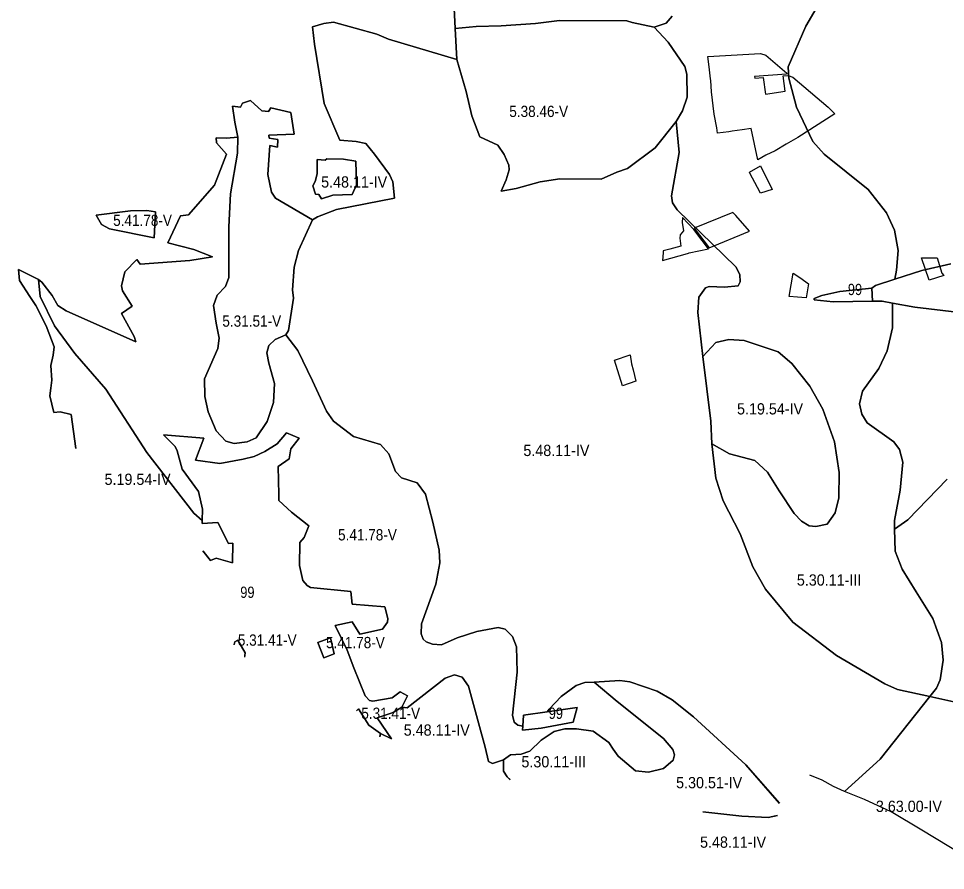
# Model space of a CAD drawing. Extents: x -589769 to -586623, y -1119592 to -1116833.
# Drawn here: x -589769 to -588124, y -1119592 to -1118080 of the extents above; entities that cross this region are included whole.
import ezdxf

# ---------------------------------------------------------------- set-up
doc = ezdxf.new("R2010")
doc.units = 0
doc.header["$LTSCALE"] = 8
doc.layers.add('40', color=7, linetype='Continuous', lineweight=25)
doc.layers.add('8', color=7, linetype='Continuous', lineweight=25)
doc.layers.add('41', color=7, linetype='Continuous')

msp = doc.modelspace()

# ---------------------------------------------------------------- linework, layer by layer
at = {"layer": '40'}
for points in [[(-588114.5, -1118516), (-588165.5, -1118527.5), (-588213.5, -1118543), (-588210.5, -1118527), (-588208, -1118492), (-588214.5, -1118456), (-588228.5, -1118425.5), (-588261, -1118384), (-588339, -1118321), (-588359.5, -1118298.5), (-588388, -1118238), (-588402, -1118186.5), (-588403, -1118166), (-588371.5, -1118094), (-588318.5, -1118002.5), (-588316, -1117995.5), (-588287.5, -1117946.5), (-588245, -1117884.5), (-588141.5, -1117767), (-588085, -1117718)], [(-588999, -1118002), (-588994, -1118098), (-588991, -1118153), (-589112.5, -1118117), (-589133, -1118108.5), (-589210, -1118087), (-589227, -1118089), (-589247, -1118095), (-589243.5, -1118126), (-589226.5, -1118231), (-589199, -1118296.5), (-589170, -1118298.5), (-589152.5, -1118302.5), (-589137, -1118321), (-589110.5, -1118357), (-589104.5, -1118370.5), (-589102, -1118399.5), (-589204.5, -1118419.5), (-589238.5, -1118432.5), (-589247, -1118438), (-589313, -1118399.5), (-589320, -1118388.5), (-589326.5, -1118357), (-589323, -1118306), (-589309.5, -1118309), (-589309, -1118295), (-589324, -1118292.5), (-589324.5, -1118287.5), (-589280, -1118285.5), (-589285.5, -1118247), (-589321, -1118239), (-589325.5, -1118245.5), (-589337, -1118244.5), (-589357, -1118226), (-589371.5, -1118230.5), (-589375, -1118238), (-589389, -1118236), (-589385, -1118264.5), (-589380, -1118291), (-589400, -1118292.5), (-589418.5, -1118292), (-589417.5, -1118301), (-589400, -1118321), (-589421, -1118376), (-589467.5, -1118429), (-589481.5, -1118430.5), (-589504, -1118478.5), (-589458, -1118490.5), (-589425, -1118503.5)], [(-588609, -1118076.5), (-588619.5, -1118088.5), (-588641, -1118096), (-588680, -1118087.5), (-588689.5, -1118084.5), (-588809, -1118084), (-588851.5, -1118089.5), (-588912.5, -1118093.5), (-588957, -1118094.5), (-588994, -1118098), (-588999, -1118002)], [(-588318.5, -1118002.5), (-588371.5, -1118094), (-588403, -1118166), (-588402, -1118186.5), (-588388, -1118238), (-588359.5, -1118298.5), (-588339, -1118321), (-588261, -1118384), (-588228.5, -1118425.5), (-588214.5, -1118456), (-588208, -1118492), (-588210.5, -1118527), (-588213.5, -1118543), (-588248, -1118554.5), (-588254.5, -1118559), (-588311.5, -1118565), (-588343.5, -1118572), (-588357, -1118577.5), (-588357, -1118580), (-588323, -1118583.5), (-588253.508, -1118582.302), (-588236, -1118582), (-588217.984, -1118585.417), (-588218, -1118629.5), (-588227, -1118670), (-588242, -1118701.5), (-588271, -1118742), (-588276.5, -1118764.5), (-588272.5, -1118782.5), (-588263, -1118798), (-588215.5, -1118832), (-588205.5, -1118845.5), (-588199.5, -1118868), (-588204, -1118917.5), (-588214, -1118971.5), (-588214.5, -1118986.5), (-588213, -1119026), (-588200.5, -1119057.5), (-588176, -1119098), (-588146, -1119145.5), (-588131, -1119188), (-588128, -1119219.5), (-588133.5, -1119254), (-588140, -1119269), (-588151.702, -1119283.819), (-588209, -1119271.5), (-588231.5, -1119261.5), (-588317, -1119211), (-588395, -1119152), (-588443.5, -1119093.5), (-588466, -1119053.5), (-588488, -1118995), (-588518.5, -1118936.5), (-588531.5, -1118896), (-588538.5, -1118835), (-588507, -1118853), (-588462, -1118865), (-588439.5, -1118885.5), (-588419, -1118918.5), (-588392.5, -1118959), (-588379.5, -1118972.5)], [(-589290, -1118634), (-589281, -1118577), (-589282.5, -1118562), (-589279.5, -1118521.5), (-589272, -1118492), (-589247, -1118438), (-589238.5, -1118432.5), (-589204.5, -1118419.5), (-589102, -1118399.5), (-589104.5, -1118370.5), (-589110.5, -1118357), (-589137, -1118321), (-589152.5, -1118302.5), (-589170, -1118298.5), (-589199, -1118296.5), (-589226.5, -1118231), (-589243.5, -1118126), (-589247, -1118095), (-589227, -1118089), (-589210, -1118087), (-589133, -1118108.5), (-589112.5, -1118117), (-588991, -1118153)], [(-588379.5, -1118972.5), (-588365.5, -1118981), (-588354, -1118982), (-588334, -1118978), (-588319.5, -1118958), (-588313, -1118931), (-588312.5, -1118886), (-588320.5, -1118832), (-588341.5, -1118773.5), (-588364.5, -1118733), (-588396.5, -1118692.5), (-588421, -1118672), (-588481, -1118652), (-588508.5, -1118650), (-588531.5, -1118655.5), (-588554.202, -1118680.024), (-588563.5, -1118602), (-588561.5, -1118575), (-588549.5, -1118558.5), (-588543, -1118556), (-588516, -1118557), (-588492, -1118555), (-588488, -1118548), (-588488.5, -1118534.5), (-588496, -1118521), (-588600, -1118420), (-588608.5, -1118407.5), (-588610, -1118395), (-588596.5, -1118318.5), (-588602, -1118263.5), (-588590.5, -1118244.5), (-588582, -1118220), (-588583, -1118179), (-588586.5, -1118165.5), (-588616, -1118122.5), (-588641, -1118096), (-588619.5, -1118088.5), (-588609, -1118076.5)], [(-588991, -1118153), (-588974.5, -1118210), (-588964.5, -1118253), (-588950.5, -1118290.5), (-588918.5, -1118305.5), (-588907, -1118322), (-588898.5, -1118341), (-588898, -1118349), (-588903.5, -1118367), (-588912.5, -1118387), (-588886, -1118382), (-588843, -1118370), (-588808.5, -1118365), (-588735, -1118365.5), (-588707, -1118353), (-588688, -1118346.5), (-588639, -1118310), (-588602, -1118263.5), (-588596.5, -1118318.5), (-588610, -1118395), (-588608.5, -1118407.5), (-588600, -1118420), (-588496, -1118521), (-588488.5, -1118534.5), (-588488, -1118548), (-588492, -1118555), (-588516, -1118557), (-588543, -1118556), (-588549.5, -1118558.5), (-588561.5, -1118575), (-588563.5, -1118602), (-588554.202, -1118680.024), (-588540.5, -1118795), (-588538.5, -1118835), (-588531.5, -1118896), (-588518.5, -1118936.5), (-588488, -1118995), (-588466, -1119053.5), (-588443.5, -1119093.5), (-588395, -1119152), (-588317, -1119211), (-588231.5, -1119261.5), (-588209, -1119271.5), (-588151.702, -1119283.819), (-588239.5, -1119395), (-588303, -1119452.5), (-588322.5, -1119443.5), (-588342.5, -1119432.5), (-588364.376, -1119423.176)], [(-589308, -1118875.5), (-589288.5, -1118862), (-589286, -1118844), (-589271, -1118825), (-589293.5, -1118816), (-589310, -1118835), (-589332, -1118849), (-589351, -1118857.5), (-589370.5, -1118862.5), (-589412, -1118870), (-589455, -1118864.5), (-589440, -1118825), (-589511.5, -1118819.5), (-589491, -1118840), (-589487.5, -1118848), (-589478.5, -1118880.5), (-589449.5, -1118920), (-589442.5, -1118951.5), (-589443, -1118971.5), (-589458, -1118958.5), (-589541.5, -1118850.5), (-589614, -1118738), (-589669, -1118675), (-589705, -1118626), (-589730.5, -1118574), (-589733.5, -1118543.5), (-589727.5, -1118548.5), (-589709.5, -1118572), (-589699, -1118590), (-589684.5, -1118599.5), (-589561, -1118654.5), (-589563.5, -1118645), (-589586, -1118604), (-589567.5, -1118591), (-589584.5, -1118564), (-589586, -1118555), (-589580.5, -1118530), (-589559, -1118508), (-589553, -1118516.5), (-589465, -1118510), (-589425, -1118503.5), (-589458, -1118490.5), (-589504, -1118478.5), (-589481.5, -1118430.5), (-589467.5, -1118429), (-589421, -1118376), (-589400, -1118321), (-589417.5, -1118301), (-589418.5, -1118292), (-589400, -1118292.5), (-589380, -1118291), (-589380.5, -1118319.5), (-589392.5, -1118391.5), (-589396, -1118450), (-589395.5, -1118540), (-589401.5, -1118556), (-589416.5, -1118571.5), (-589423, -1118589.5), (-589418, -1118621), (-589413, -1118648), (-589415, -1118666), (-589439, -1118720), (-589438.5, -1118751.5), (-589432.5, -1118778.5), (-589418.5, -1118812), (-589401, -1118830.5), (-589386.5, -1118834.5), (-589363.5, -1118832), (-589347.5, -1118824.5), (-589327.5, -1118795.5), (-589316.5, -1118762), (-589314.5, -1118728), (-589324.5, -1118692), (-589328.5, -1118674), (-589325, -1118660.5), (-589313.5, -1118650), (-589294.5, -1118642)], [(-589425, -1118503.5), (-589465, -1118510), (-589553, -1118516.5), (-589559, -1118508), (-589580.5, -1118530), (-589586, -1118555), (-589584.5, -1118564), (-589567.5, -1118591), (-589586, -1118604), (-589563.5, -1118645), (-589561, -1118654.5), (-589684.5, -1118599.5), (-589699, -1118590), (-589709.5, -1118572), (-589727.5, -1118548.5), (-589733.5, -1118543.5), (-589769, -1118526), (-589767.5, -1118545.5), (-589749, -1118574), (-589738.5, -1118590), (-589720, -1118626), (-589706, -1118663), (-589707.5, -1118678), (-589711.5, -1118696), (-589710, -1118722.5), (-589711.5, -1118736.5), (-589713.5, -1118750), (-589706.5, -1118779.5), (-589695, -1118778.5), (-589675.5, -1118783), (-589667.5, -1118843.5)], [(-589667.5, -1118843.5), (-589675.5, -1118783), (-589695, -1118778.5), (-589706.5, -1118779.5), (-589713.5, -1118750), (-589711.5, -1118736.5), (-589710, -1118722.5), (-589711.5, -1118696), (-589707.5, -1118678), (-589706, -1118663), (-589720, -1118626), (-589738.5, -1118590), (-589749, -1118574), (-589767.5, -1118545.5), (-589769, -1118526), (-589733.5, -1118543.5), (-589730.5, -1118574), (-589705, -1118626), (-589669, -1118675), (-589614, -1118738), (-589541.5, -1118850.5), (-589458, -1118958.5), (-589443, -1118971.5), (-589443, -1118976.5), (-589415, -1118975), (-589396.5, -1119012), (-589388.5, -1119011.5), (-589389, -1119046.5), (-589418.5, -1119038.5), (-589428.5, -1119042.5), (-589441.679, -1119025.337)], [(-587905, -1118625), (-588178, -1118593), (-588217.984, -1118585.417), (-588236, -1118582), (-588253.508, -1118582.302), (-588254.5, -1118559), (-588248, -1118554.5), (-588213.5, -1118543), (-588165.5, -1118527.5), (-588114.5, -1118516)], [(-588120.5, -1118898), (-588190.5, -1118970), (-588214.5, -1118986.5), (-588214, -1118971.5), (-588204, -1118917.5), (-588199.5, -1118868), (-588205.5, -1118845.5), (-588215.5, -1118832), (-588263, -1118798), (-588272.5, -1118782.5), (-588276.5, -1118764.5), (-588271, -1118742), (-588242, -1118701.5), (-588227, -1118670), (-588218, -1118629.5), (-588217.984, -1118585.417), (-588178, -1118593), (-587905, -1118625)], [(-589294.5, -1118642), (-589273, -1118669.5), (-589247, -1118723.5), (-589222.5, -1118777.5), (-589210, -1118795), (-589174.5, -1118822), (-589126.5, -1118836.5), (-589111.5, -1118853), (-589100, -1118884.5), (-589089, -1118895.5), (-589061.5, -1118904.5), (-589046.5, -1118924.5), (-589033.5, -1118974.5), (-589022.5, -1119024), (-589021, -1119046.5), (-589028.5, -1119084.5), (-589053.5, -1119154.5), (-589054.5, -1119172.5), (-589051, -1119182), (-589045.5, -1119187), (-589034.5, -1119191), (-589018, -1119192), (-588990.5, -1119179.5), (-588955.5, -1119168.5), (-588917.5, -1119161.5), (-588905.5, -1119164.5), (-588892, -1119177.5), (-588885, -1119195.5), (-588884, -1119240.5), (-588892.5, -1119317), (-588889.5, -1119329), (-588883, -1119334.5), (-588873.972, -1119336.502), (-588874.5, -1119343.5), (-588841.5, -1119340), (-588784.5, -1119329), (-588777.5, -1119303.5), (-588830.496, -1119311.031), (-588827, -1119306), (-588806, -1119283.5), (-588779.5, -1119264.5), (-588764, -1119259), (-588747.5, -1119258), (-588706.5, -1119292.5), (-588624.5, -1119358.5), (-588607.5, -1119378), (-588604.5, -1119387), (-588607, -1119397), (-588624.5, -1119411.5), (-588651, -1119418), (-588674, -1119415.5), (-588704.5, -1119389.5), (-588713.5, -1119377), (-588721.5, -1119365.5), (-588749, -1119345.5), (-588778.5, -1119341), (-588799.5, -1119341), (-588818.5, -1119346), (-588841.5, -1119361), (-588861.5, -1119381), (-588877, -1119386), (-588896, -1119387.5), (-588908, -1119396), (-588927.5, -1119402.5), (-588935, -1119399), (-588940.5, -1119373.5), (-588952.5, -1119330.5), (-588970.5, -1119265.5), (-588981.5, -1119249.5), (-588995, -1119245.5), (-589012, -1119251), (-589079, -1119304), (-589088.5, -1119302.5), (-589078.5, -1119282.5), (-589091.5, -1119275.5), (-589106, -1119286), (-589140, -1119292), (-589146, -1119291), (-589154, -1119282.5), (-589174, -1119233), (-589185.5, -1119201.5), (-589207, -1119157.5), (-589177, -1119151), (-589163.5, -1119173), (-589123, -1119164.5), (-589114, -1119152), (-589113.5, -1119145), (-589119, -1119124.5), (-589177, -1119120), (-589179.5, -1119097.5), (-589251, -1119090.5), (-589256.5, -1119087), (-589264.5, -1119078), (-589270.5, -1119051), (-589270, -1119010.5), (-589262, -1119001.5), (-589253.5, -1118981), (-589284.5, -1118956.5), (-589307, -1118936), (-589307, -1118925), (-589308, -1118875.5)], [(-588418.315, -1119473.349), (-588478, -1119405), (-588571, -1119320), (-588609, -1119289.5), (-588635.5, -1119274.5), (-588684, -1119257.5), (-588702, -1119255.5), (-588747.5, -1119258), (-588764, -1119259), (-588779.5, -1119264.5), (-588806, -1119283.5), (-588827, -1119306), (-588830.496, -1119311.031), (-588872.5, -1119317), (-588873.972, -1119336.502), (-588883, -1119334.5), (-588889.5, -1119329), (-588892.5, -1119317), (-588884, -1119240.5), (-588885, -1119195.5), (-588892, -1119177.5), (-588905.5, -1119164.5), (-588917.5, -1119161.5), (-588955.5, -1119168.5), (-588990.5, -1119179.5), (-589018, -1119192), (-589034.5, -1119191), (-589045.5, -1119187), (-589051, -1119182), (-589054.5, -1119172.5), (-589053.5, -1119154.5), (-589028.5, -1119084.5), (-589021, -1119046.5), (-589022.5, -1119024), (-589033.5, -1118974.5), (-589046.5, -1118924.5), (-589061.5, -1118904.5), (-589089, -1118895.5), (-589100, -1118884.5), (-589111.5, -1118853), (-589126.5, -1118836.5), (-589174.5, -1118822), (-589210, -1118795), (-589222.5, -1118777.5), (-589247, -1118723.5), (-589273, -1118669.5), (-589294.5, -1118642), (-589290, -1118634)], [(-589441.473, -1119025.605), (-589428.5, -1119042.5), (-589418.5, -1119038.5), (-589389, -1119046.5), (-589388.5, -1119011.5), (-589396.5, -1119012), (-589415, -1118975), (-589443, -1118976.5), (-589443, -1118971.5), (-589442.5, -1118951.5), (-589449.5, -1118920), (-589478.5, -1118880.5), (-589487.5, -1118848), (-589491, -1118840), (-589511.5, -1118819.5), (-589440, -1118825), (-589455, -1118864.5), (-589412, -1118870), (-589370.5, -1118862.5), (-589351, -1118857.5), (-589332, -1118849), (-589310, -1118835), (-589293.5, -1118816), (-589271, -1118825), (-589286, -1118844), (-589288.5, -1118862), (-589308, -1118875.5), (-589307, -1118925), (-589307, -1118936), (-589284.5, -1118956.5), (-589253.5, -1118981), (-589262, -1119001.5), (-589270, -1119010.5), (-589270.5, -1119051), (-589264.5, -1119078), (-589256.5, -1119087), (-589251, -1119090.5), (-589179.5, -1119097.5), (-589177, -1119120), (-589119, -1119124.5), (-589113.5, -1119145), (-589114, -1119152), (-589123, -1119164.5), (-589163.5, -1119173), (-589177, -1119151), (-589207, -1119157.5), (-589185.5, -1119201.5), (-589174, -1119233), (-589154, -1119282.5), (-589146, -1119291), (-589140, -1119292), (-589106, -1119286), (-589091.5, -1119275.5), (-589078.5, -1119282.5), (-589088.5, -1119302.5)], [(-588109, -1119293), (-588151.702, -1119283.819), (-588140, -1119269), (-588133.5, -1119254), (-588128, -1119219.5), (-588131, -1119188), (-588146, -1119145.5), (-588176, -1119098), (-588200.5, -1119057.5), (-588213, -1119026), (-588214.5, -1118986.5), (-588190.5, -1118970), (-588120.5, -1118898)], [(-589386.576, -1119192.174), (-589385, -1119186.5), (-589379.5, -1119183.5), (-589367, -1119206.5), (-589367.5, -1119211), (-589367.464, -1119212.277)], [(-589367.423, -1119213.701), (-589367.5, -1119211), (-589367, -1119206.5), (-589379.5, -1119183.5), (-589385, -1119186.5), (-589386.311, -1119191.221)], [(-589127.694, -1119354.765), (-589126.5, -1119349.5), (-589107, -1119359), (-589132.5, -1119321.5), (-589104, -1119312), (-589088.5, -1119302.5), (-589079, -1119304), (-589012, -1119251), (-588995, -1119245.5), (-588981.5, -1119249.5), (-588970.5, -1119265.5), (-588952.5, -1119330.5), (-588940.5, -1119373.5), (-588935, -1119399), (-588927.5, -1119402.5), (-588908, -1119396), (-588908, -1119416), (-588901.5, -1119426.5), (-588896.548, -1119431.104)], [(-588713.5, -1119377), (-588704.5, -1119389.5), (-588674, -1119415.5), (-588651, -1119418), (-588624.5, -1119411.5), (-588607, -1119397), (-588604.5, -1119387), (-588607.5, -1119378), (-588624.5, -1119358.5), (-588706.5, -1119292.5), (-588747.5, -1119258), (-588702, -1119255.5), (-588684, -1119257.5), (-588635.5, -1119274.5), (-588609, -1119289.5), (-588571, -1119320), (-588478, -1119405), (-588418.489, -1119473.15)], [(-588047.479, -1119592.482), (-588166, -1119521), (-588220, -1119488.5), (-588267.5, -1119466.5), (-588303, -1119452.5), (-588239.5, -1119395), (-588151.702, -1119283.819), (-588109, -1119293)], [(-589088.5, -1119302.5), (-589104, -1119312), (-589132.5, -1119321.5), (-589107, -1119359), (-589126.5, -1119349.5), (-589147.5, -1119334.5), (-589165.5, -1119305.5), (-589169.102, -1119309.346)], [(-589168.547, -1119308.754), (-589165.5, -1119305.5), (-589147.5, -1119334.5), (-589126.5, -1119349.5), (-589127.818, -1119355.313)], [(-588896.148, -1119431.476), (-588901.5, -1119426.5), (-588908, -1119416), (-588908, -1119396), (-588896, -1119387.5), (-588877, -1119386), (-588861.5, -1119381), (-588841.5, -1119361), (-588818.5, -1119346), (-588799.5, -1119341), (-588778.5, -1119341), (-588749, -1119345.5), (-588721.5, -1119365.5), (-588713.5, -1119377)], [(-588554.421, -1119488.71), (-588485.5, -1119496), (-588438.5, -1119498.5), (-588421.837, -1119494.842)], [(-588422.555, -1119495), (-588438.5, -1119498.5), (-588485.5, -1119496), (-588554.363, -1119488.716)]]:
    msp.add_lwpolyline(points, dxfattribs=at)
for points in [[(-588641, -1118096), (-588616, -1118122.5), (-588586.5, -1118165.5), (-588583, -1118179), (-588582, -1118220), (-588590.5, -1118244.5), (-588602, -1118263.5), (-588639, -1118310), (-588688, -1118346.5), (-588707, -1118353), (-588735, -1118365.5), (-588808.5, -1118365), (-588843, -1118370), (-588886, -1118382), (-588912.5, -1118387), (-588903.5, -1118367), (-588898, -1118349), (-588898.5, -1118341), (-588907, -1118322), (-588918.5, -1118305.5), (-588950.5, -1118290.5), (-588964.5, -1118253), (-588974.5, -1118210), (-588991, -1118153), (-588994, -1118098), (-588957, -1118094.5), (-588912.5, -1118093.5), (-588851.5, -1118089.5), (-588809, -1118084), (-588689.5, -1118084.5), (-588680, -1118087.5)], [(-589247, -1118438), (-589272, -1118492), (-589279.5, -1118521.5), (-589282.5, -1118562), (-589281, -1118577), (-589290, -1118634), (-589294.5, -1118642), (-589313.5, -1118650), (-589325, -1118660.5), (-589328.5, -1118674), (-589324.5, -1118692), (-589314.5, -1118728), (-589316.5, -1118762), (-589327.5, -1118795.5), (-589347.5, -1118824.5), (-589363.5, -1118832), (-589386.5, -1118834.5), (-589401, -1118830.5), (-589418.5, -1118812), (-589432.5, -1118778.5), (-589438.5, -1118751.5), (-589439, -1118720), (-589415, -1118666), (-589413, -1118648), (-589418, -1118621), (-589423, -1118589.5), (-589416.5, -1118571.5), (-589401.5, -1118556), (-589395.5, -1118540), (-589396, -1118450), (-589392.5, -1118391.5), (-589380.5, -1118319.5), (-589380, -1118291), (-589385, -1118264.5), (-589389, -1118236), (-589375, -1118238), (-589371.5, -1118230.5), (-589357, -1118226), (-589337, -1118244.5), (-589325.5, -1118245.5), (-589321, -1118239), (-589285.5, -1118247), (-589280, -1118285.5), (-589324.5, -1118287.5), (-589324, -1118292.5), (-589309, -1118295), (-589309.5, -1118309), (-589323, -1118306), (-589326.5, -1118357), (-589320, -1118388.5), (-589313, -1118399.5)], [(-589222, -1118329.5), (-589224.5, -1118332), (-589239, -1118330.5), (-589239, -1118356), (-589242.5, -1118369.5), (-589246.5, -1118377.5), (-589242, -1118392), (-589236, -1118392.5), (-589231, -1118400.5), (-589211, -1118394), (-589177, -1118393), (-589169, -1118375.5), (-589170.5, -1118333.5), (-589192, -1118330)], [(-589192, -1118330), (-589170.5, -1118333.5), (-589169, -1118375.5), (-589177, -1118393), (-589211, -1118394), (-589231, -1118400.5), (-589236, -1118392.5), (-589242, -1118392), (-589246.5, -1118377.5), (-589242.5, -1118369.5), (-589239, -1118356), (-589239, -1118330.5), (-589224.5, -1118332), (-589222, -1118329.5)], [(-589607.5, -1118453.5), (-589528.5, -1118469.5), (-589526, -1118423.5), (-589541, -1118421), (-589570, -1118421.5), (-589631.5, -1118429.5), (-589621.5, -1118446)], [(-589526, -1118423.5), (-589528.5, -1118469.5), (-589607.5, -1118453.5), (-589621.5, -1118446), (-589631.5, -1118429.5), (-589570, -1118421.5), (-589541, -1118421)], [(-588253.508, -1118582.302), (-588323, -1118583.5), (-588357, -1118580), (-588357, -1118577.5), (-588343.5, -1118572), (-588311.5, -1118565), (-588254.5, -1118559)], [(-588538.5, -1118835), (-588540.5, -1118795), (-588554.202, -1118680.024), (-588531.5, -1118655.5), (-588508.5, -1118650), (-588481, -1118652), (-588421, -1118672), (-588396.5, -1118692.5), (-588364.5, -1118733), (-588341.5, -1118773.5), (-588320.5, -1118832), (-588312.5, -1118886), (-588313, -1118931), (-588319.5, -1118958), (-588334, -1118978), (-588354, -1118982), (-588365.5, -1118981), (-588379.5, -1118972.5), (-588392.5, -1118959), (-588419, -1118918.5), (-588439.5, -1118885.5), (-588462, -1118865), (-588507, -1118853)], [(-589209, -1119208), (-589215.5, -1119179.5), (-589237.5, -1119188), (-589227, -1119215)], [(-589209, -1119208), (-589227, -1119215), (-589237.5, -1119188), (-589215.5, -1119179.5)], [(-588873.972, -1119336.502), (-588872.5, -1119317), (-588830.496, -1119311.031), (-588777.5, -1119303.5), (-588784.5, -1119329), (-588841.5, -1119340), (-588874.5, -1119343.5)]]:
    msp.add_lwpolyline(points, close=True, dxfattribs=at)
at = {"layer": '8'}
for points in [[(-588319.97, -1118249.32), (-588385.67, -1118291.34), (-588406.8, -1118303.29), (-588426.09, -1118315.45), (-588442.39, -1118323.14), (-588456.87, -1118331.51), (-588468.82, -1118275.59), (-588484.64, -1118277.93), (-588502.58, -1118280.59), (-588508.23, -1118281.43), (-588528.224, -1118283.969), (-588529.35, -1118274.66), (-588534.32, -1118250.35), (-588539.16, -1118210.75), (-588540.17, -1118190.18), (-588540.83, -1118187.61), (-588543.34, -1118166.3), (-588545.5, -1118147.9), (-588452.37, -1118142.81), (-588442.78, -1118145.68), (-588405.64, -1118177.25), (-588406.2, -1118178.91), (-588462.46, -1118183.55), (-588462.32, -1118186.55), (-588447.22, -1118185.31), (-588443.02, -1118214.61), (-588408.31, -1118209.31), (-588412.04, -1118182.4), (-588403.13, -1118181.67), (-588394.44, -1118184.61), (-588332.01, -1118237.68)], [(-588452.02, -1118342.01), (-588431.15, -1118384.02), (-588452.185, -1118390.555), (-588457.62, -1118380.46), (-588470.87, -1118354.91), (-588471.83, -1118353.1)], [(-588501.37, -1118424.43), (-588569.89, -1118452.8), (-588543.11, -1118487.4), (-588471.59, -1118457.8), (-588495.83, -1118430.28)], [(-588590.53, -1118433.3), (-588591.14, -1118442.39), (-588588.69, -1118457.09), (-588594.4, -1118464.58), (-588595.16, -1118470.11), (-588593.48, -1118484.31), (-588612.89, -1118489.59), (-588624.7, -1118492.79), (-588624.99, -1118496.59), (-588625.86, -1118510.11), (-588581.67, -1118497.53), (-588579.6, -1118496.72), (-588578.55, -1118496.3), (-588544.44, -1118488.93), (-588555.74, -1118474.35), (-588559.91, -1118468.94), (-588570.63, -1118455.02)], [(-588126.62, -1118536.69), (-588153.012, -1118544.907), (-588166.483, -1118505.266), (-588138.57, -1118505.13), (-588130.05, -1118532.13)], [(-588386.456, -1118574.79), (-588401.495, -1118573.725), (-588394.28, -1118532.18), (-588380.681, -1118541.538), (-588366.71, -1118551.14), (-588370.982, -1118576.053)], [(-588711.11, -1118686.55), (-588683.59, -1118677.21), (-588680.98, -1118693.31), (-588678.38, -1118704.02), (-588673.21, -1118723.89), (-588697.04, -1118732.42)]]:
    msp.add_lwpolyline(points, close=True, dxfattribs=at)

# ---------------------------------------------------------------- texts
at = {"layer": '41'}
for s, width, p in [('5.38.46-V', 0.9, (-588897.967, -1118255.256)), ('5.48.11-IV', 0.95, (-589231.866, -1118380.479)), ('5.41.78-V', 0.9, (-589601.085, -1118448.567)), ('99', 0.85, (-588297.031, -1118571.25)), ('5.31.51-V', 0.9, (-589407.238, -1118627.432)), ('5.19.54-IV', 0.95, (-588493.728, -1118783.173)), ('5.48.11-IV', 0.95, (-588872.952, -1118856.988)), ('5.19.54-IV', 0.95, (-589616.323, -1118908.202)), ('5.41.78-V', 0.9, (-589201.868, -1119006.74)), ('5.30.11-III', 0.95, (-588387.537, -1119086.93)), ('99', 0.85, (-589375.462, -1119108.716)), ('5.31.41-V', 0.9, (-589379.727, -1119193.601)), ('5.41.78-V', 0.9, (-589223.25, -1119198)), ('5.31.41-V', 0.9, (-589160.592, -1119323.45)), ('99', 0.85, (-588828, -1119323.5)), ('5.48.11-IV', 0.95, (-589085.312, -1119353.312)), ('5.30.11-III', 0.95, (-588876.377, -1119409.543)), ('5.30.51-IV', 0.95, (-588601.868, -1119446.621)), ('3.63.00-IV', 0.95, (-588247.266, -1119488.597)), ('5.48.11-IV', 0.95, (-588559.393, -1119552.214))]:
    msp.add_text(s, height=20, dxfattribs=dict(at, width=width)).set_placement(p)

doc.saveas('drawing.dxf')
